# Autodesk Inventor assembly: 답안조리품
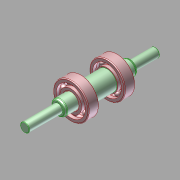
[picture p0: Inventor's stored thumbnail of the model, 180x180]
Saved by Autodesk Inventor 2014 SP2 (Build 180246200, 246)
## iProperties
Created: 2024-04
Part Number: 답안조리품
Document SubType Name: Assembly
Designer: Administrator
Author: Administrator
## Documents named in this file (4)
- C:\Users\Administrator\Desktop\740404V1007\답안조리품.iam
- C:\Users\Administrator\Desktop\740404V1007\본체.ipt
- C:\Users\Administrator\Desktop\740404V1007\가져온 구성요소\깊은 홈 볼 베어링 6204\깊은 홈 볼 베어링 6204.ipt
- C:\Users\Administrator\Desktop\740404V1007\가져온 구성요소\축\축.ipt
